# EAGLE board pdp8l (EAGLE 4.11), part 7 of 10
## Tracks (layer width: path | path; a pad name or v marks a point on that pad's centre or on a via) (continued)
N$34  (via drill 0.61) (continued)
  Route2 0.203: v25.6,207.52 25.6,207.92 v57.3,239.62
  Route15 0.203: v9.75,135.59 34.14,111.2 35.76,111.2 C34.K1
  Bottom 0.203: v7.32,197.76 8.13,198.58 16.26,198.58 25.2,207.52 v25.6,207.52 | v57.3,239.62 57.71,240.03 73.15,240.03 73.97,240.84 AB31.AM1
N$35  (via drill 0.61)
  Top 0.203: v7.72,112.01 6.5,113.23 6.5,134.77 7.32,135.59 7.32,147.78 6.1,149 6.1,203.05 12.19,209.14 12.19,216.86 10.97,218.08 v10.97,219.71
  Route2 0.203: v56.49,220.12 68.68,232.31 68.68,233.12 69.49,233.93 69.49,235.97 71.12,237.59 AB31.AN1
  Bottom 0.203: v7.72,112.01 13.01,106.73 32.11,106.73 32.92,107.54 C34.L1 | v10.97,219.71 11.38,219.3 12.19,219.3 13.82,217.68 48.77,217.68 51.61,220.52 56.08,220.52 v56.49,220.12
N$36  (via drill 0.61)
  Top 0.203: v310.9,55.12 310.9,38.05 311.71,37.24 311.71,33.17 312.52,32.36 D12.N1
  Route15 0.203: v310.9,55.12 306.02,60 303.99,60 D13.C1
N$37
  Route2 0.203: D12.F1 312.93,51.46 312.93,53.09 334.06,74.22 335.69,74.22 343,81.53 343,83.16 343.81,83.97 345.85,83.97 347.07,85.19 C09.U2
N$38  (via drill 0.61)
  Top 0.203: v343.81,86 343.81,83.57 344.22,83.16 C09.V2 | v326.34,103.48 325.53,104.29 325.53,107.14 C11.L1
  Route15 0.203: v343.81,86 v326.34,103.48
N$39
  Top 0.203: A08.M2 359.66,241.66 357.63,243.69 357.63,244.09 A08.L2
  Route2 0.203: A10.R1 338.53,232.31 338.53,233.93 340.16,235.56 340.16,235.97 343.81,239.62 347.88,239.62 349.1,240.84 351.54,240.84 353.16,242.47 354.79,242.47 356.41,244.09 A08.L2
N$40  (via drill 0.61)
  Top 0.203: v102.01,259.54 102.01,235.56 117.04,220.52 117.04,211.99 117.45,211.58 117.45,136.8 112.98,132.33 112.98,130.71 C28.C1
  Bottom 0.203: v102.01,259.54 101.6,259.13 99.57,259.13 96.72,261.98 25.6,261.98 24.38,260.76 A35.E1
N$41  (via drill 0.61)
  Top 0.203: v307.24,131.93 307.64,132.33 307.64,142.49 308.05,142.9 308.05,147.37 307.64,147.78 307.64,159.16 307.24,159.56 307.24,160.78 307.64,161.19 v307.64,184.35 | v347.47,236.78 347.47,240.84 A09.M2 | v323.9,212.39 323.9,201.83 v321.87,199.8
  Route2 0.203: v307.64,184.35 312.12,188.82 314.15,188.82 315.37,190.04 B12.E1 316.18,191.26 317.81,192.89 317.81,195.73 v321.87,199.8 | v347.47,236.78 347.07,236.78 330.4,220.12 330.4,218.9 v323.9,212.39
  Route15 0.203: v307.24,131.93 308.05,131.12 308.05,129.9 308.46,129.49 308.46,129.08 310.49,127.05 310.49,125.83 310.9,125.42 311.3,125.42 316.18,120.55 316.18,120.14 316.59,119.74 316.18,119.33 314.96,119.33 314.15,120.14 313.33,120.14 C12.F1
N$42  (via drill 0.61)
  Route2 0.203: v315.37,120.14 313.33,118.11 313.33,114.86 C12.J1 | v251.97,211.99 251.97,213.21 280.42,241.66 280.42,242.06 280.82,242.47 282.45,242.47 286.11,246.13 286.92,246.13 289.76,248.97 293.83,248.97 317.4,272.54 v317.4,273.76
  Route15 0.203: v315.37,120.14 310.08,125.42 310.08,126.64 308.05,128.68 308.05,129.08 299.92,137.21 299.92,142.9 297.89,144.93 297.89,146.15 296.67,147.37 296.67,149.4 295.86,150.22 295.86,151.44 289.36,157.94 289.36,162 273.51,177.85 273.1,177.85 269.85,181.1 269.85,182.73 264.97,187.6 264.97,188.42 254.41,198.98 254.41,203.45 254,203.86 254,209.96 v251.97,211.99 | v317.4,273.76 317.4,276.61 314.55,279.45 314.55,280.26 318.21,283.92 334.87,283.92 353.57,265.23 354.79,265.23 356.41,263.6 A08.D2
N$43  (via drill 0.61)
  Top 0.203: v327.96,180.29 330,180.29 330,188.01 v329.59,188.42 | v345.03,204.27 347.07,206.3 351.13,206.3 351.13,204.27 v351.94,203.45 | v355.6,220.12 357.23,221.74 357.23,223.77 356.82,224.18 356.01,224.18 356.01,227.43 357.23,228.65 357.23,231.09 A08.R2
  Route2 0.203: v303.99,112.83 303.99,115.27 308.05,119.33 308.05,120.14 314.15,126.24 314.15,127.05 v315.37,128.27 | v305.61,143.31 305.61,145.75 320.65,160.78 320.65,161.59 323.49,164.44 323.49,175.82 v327.96,180.29 | v329.59,188.42 329.59,188.82 v345.03,204.27 | v351.13,215.24 351.13,215.65 v355.6,220.12
  Route15 0.203: v303.99,112.83 312.52,104.29 312.52,102.26 C12.N1 | v315.37,128.27 315.37,128.68 314.55,129.49 314.55,133.55 306.02,142.09 306.02,142.9 v305.61,143.31 | v351.94,203.45 351.13,204.27 351.13,205.89 350.72,206.3 350.72,207.52 353.16,209.96 352.75,210.36 352.75,211.99 351.13,213.61 v351.13,215.24
N$44  (via drill 0.61)
  Top 0.203: v278.79,132.74 279.2,133.15 279.2,138.84 274.32,143.71 274.32,147.37 273.51,148.18 273.51,158.75 v273.91,159.16 | v316.59,231.5 v315.37,232.72
  Route2 0.203: v255.63,177.44 255.63,177.85 262.53,184.76 263.75,184.76 293.83,214.83 294.64,214.83 295.45,215.65 298.7,215.65 299.52,216.46 301.55,216.46 v316.59,231.5 | v315.37,232.72 315.77,232.72 317.4,234.34 317.4,238.4 v329.59,250.6
  Route15 0.203: v278.79,132.74 278.79,132.33 299.92,111.2 299.92,108.76 C13.L1 | v255.63,177.44 v273.91,159.16 | v329.59,250.6 330,250.6 340.56,240.03 342.19,240.03 343.81,238.4 A09.N2
N$45  (via drill 0.61)
  Top 0.203: A08.H2 360.07,254.66 360.07,259.54 A08.E2 | v342.6,156.72 343,157.12 343,255.88 343.81,256.69 A09.F2 344.22,257.91 344.22,262.79 A09.D2 | A09.E2 347.47,259.54 347.47,254.66 A09.H2
  Bottom 0.203: A08.F2 357.63,257.5 359.66,259.54 360.07,259.54 A08.E2 | v342.6,156.72 333.25,156.72 332.44,155.91 B10.T2 | 346.66,255.47 345.44,256.69 345.03,256.69 A09.F2 | 346.66,255.47 347.47,254.66 A09.H2 | 346.66,255.47 358.44,255.47 359.66,254.25 A08.H2
N$46
  Top 0.203: C13.H1 302.77,118.11 302.77,121.36 301.95,122.17 301.95,137.62 303.17,138.84 303.17,150.62 301.95,151.84 301.95,195.33 302.77,196.14 B13.C1
N$47  (via drill 0.61)
  Top 0.203: v342.19,248.97 342.6,248.56 342.6,164.44 340.16,162 340.16,151.44 340.56,151.03 340.56,139.24 339.75,138.43 339.75,90.88 340.16,90.47 340.16,82.75 342.6,80.31 342.6,39.68 343,39.27 343,25.04 343.41,24.64 343.41,20.57 344.22,19.76 D09.T2 | A09.H1 353.57,253.44 351.54,251.41 351.54,251 A09.J1
  Bottom 0.203: v342.19,248.97 346.25,248.97 347.47,250.19 350.32,250.19 A09.J1
N$48  (via drill 0.61)
  Top 0.203: v340.16,33.17 340.16,25.86 342.6,23.42 342.6,14.88 344.22,13.26 D09.V2
  Bottom 0.203: v340.16,33.17 340.56,33.58 346.25,33.58 347.07,34.39 D09.M2
N$49  (via drill 0.61)
  Top 0.203: A09.S2 347.47,227.84 347.47,222.96 A09.U2 347.07,221.74 345.03,221.74 345.03,224.99 A09.T2 344.22,226.21 344.22,231.09 A09.R2 | v330.4,32.77 330.4,72.19 329.18,73.41 329.18,84.38 330.4,85.6 330.4,103.48 v330.81,103.89 | v338.53,111.61 339.34,112.42 339.34,138.84 338.94,139.24 338.94,147.78 339.34,148.18 339.34,223.77 v340.56,224.99
  Route2 0.203: v338.53,111.61 v330.81,103.89
  Bottom 0.203: v330.4,32.77 326.34,32.77 325.93,32.36 D11.N1 | v340.56,224.99 343.81,224.99 A09.T2
N$50  (via drill 0.61)
  Top 0.203: A09.P1 353.57,235.56 353.57,240.84 A09.M1 | v324.31,215.24 324.71,214.83 324.71,201.83 323.49,200.61 323.49,99.82 322.68,99.01 C11.P2 | v349.5,215.24 349.5,227.43 350.72,228.65 350.72,231.09 A09.R1 350.72,232.31 350.72,237.59 A09.N1
  Route2 0.203: A09.P1 353.57,234.34 353.16,234.34 351.13,232.31 A09.R1
  Bottom 0.203: v324.31,215.24 324.71,215.65 349.1,215.65 v349.5,215.24
N$51  (via drill 0.61)
  Top 0.203: v320.65,131.93 v320.65,85.6 | v324.31,131.93 323.9,132.33 323.9,191.67 v324.31,192.07 | v321.87,192.07 321.06,192.89 v321.06,205.08 | v354.79,205.08 354.79,220.93 355.6,221.74 355.6,251.82 356.01,252.22 v356.01,261.57 | A08.A1 366.17,272.54 364.95,271.32 364.95,264.82 364.13,264.01 A08.D1
  Route2 0.203: v324.31,192.07 v321.87,192.07
  Route15 0.203: v324.31,131.93 v320.65,131.93
  Bottom 0.203: v320.65,85.6 316.59,85.6 C12.U1 | v321.06,205.08 321.46,205.49 354.38,205.49 v354.79,205.08 | v356.01,261.57 356.41,261.98 361.7,261.98 362.92,263.2 A08.D1
N$52  (via drill 0.61)
  Top 0.203: v305.21,185.98 305.21,185.57 304.39,184.76 304.39,179.07 303.58,178.26 B13.K1
  Bottom 0.203: v305.21,185.98 311.3,185.98 312.12,186.79 B12.F1
N$53  (via drill 0.61)
  Top 0.203: v273.51,169.32 273.51,167.28 273.91,166.88 273.91,163.22 273.1,162.41 273.1,147.78 273.91,146.96 273.91,142.49 273.51,142.09 273.51,122.17 274.32,121.36 C15.F1
  Route2 0.203: v273.51,169.32 273.51,169.72 v293.01,189.23
  Bottom 0.203: v293.01,189.23 295.45,189.23 296.27,190.04 B13.E2
N$54
  Bottom 0.203: B14.J2 280.82,180.29 280.82,175.82 280.01,175.82 279.6,175.41 279.6,173.38 311.3,173.38 312.12,174.19 B12.L1
N$55  (via drill 0.61)
  Top 0.203: v311.3,220.12 v311.3,228.65
  Bottom 0.203: v311.3,220.12 310.9,220.52 295.45,220.52 294.23,219.3 A13.V2 | v311.3,228.65 315.37,228.65 A12.S1
N$56  (via drill 0.61)
  Top 0.203: v293.01,179.48 292.2,180.29 292.2,204.67 290.98,205.89 290.98,220.12 292.2,221.34 v292.2,246.13 | A08.K1 366.17,248.16 366.17,248.56 364.13,250.6 A08.J1 364.13,251 364.13,251.41 366.17,253.44 A08.H1 366.17,254.25 366.17,254.66 364.13,256.69 A08.F1
  Route15 0.203: v293.01,179.48 294.23,178.26 296.27,178.26 B13.K2
  Bottom 0.203: v292.2,246.13 364.95,246.13 366.17,247.34 A08.K1
N$57  (via drill 0.61)
  Top 0.203: B09.H2 347.47,184.76 347.47,190.04 B09.E2 | B09.F2 344.22,188.01 344.22,192.89 B09.D2 | v323.09,207.92 323.09,212.8 323.49,213.21 323.49,252.63 322.68,253.44 A11.H2
  Route15 0.203: v323.09,207.92 323.09,206.7 334.47,195.33 335.28,195.33 336.91,193.7 336.91,192.89 340.56,189.23 342.19,189.23 343.81,187.6 B09.F2 345.03,186.79 347.07,184.76 347.07,184.35 B09.H2
N$58
  Top 0.203: B12.M1 316.18,172.16 317.4,173.38 317.4,185.57 316.99,185.98 316.99,189.64 317.4,190.04 317.4,271.32 316.18,272.54 A12.A1
N$59  (via drill 0.61)
  Top 0.203: B09.M2 347.47,172.16 347.47,177.04 B09.K2 | B09.N2 344.22,168.91 344.22,174.19 B09.L2 | v324.31,240.84 324.31,222.15 326.75,219.71 326.75,202.23 327.15,201.83 327.15,175.41 v327.56,175.01
  Route2 0.203: v324.31,240.84 322.68,240.84 A11.M2
  Bottom 0.203: v327.56,175.01 329.18,173.38 340.97,173.38 341.78,174.19 343.81,174.19 B09.L2 345.03,175.01 345.44,175.01 347.47,177.04 B09.K2
N$60  (via drill 0.61)
  Top 0.203: B09.N1 350.32,167.69 350.32,162.41 B09.R1 | v328.78,199.39 328.78,201.02 327.15,202.64 327.15,244.5 325.53,246.13 325.53,250.19 A11.J1 | B09.P1 353.57,165.66 353.57,170.94 B09.M1
  Route15 0.203: v328.78,199.39 353.57,174.6 353.57,172.16 B09.M1
  Bottom 0.203: B09.R1 351.13,162.41 353.16,164.44 353.57,164.44 B09.P1
N$61  (via drill 0.61)
  Top 0.203: B09.U2 347.07,152.65 345.03,154.69 345.03,155.09 B09.T2 345.03,155.91 345.03,156.31 347.07,158.34 B09.S2 347.07,159.16 345.03,161.19 345.03,161.59 B09.R2 | v330.4,170.13 330.4,188.82 330,189.23 330,201.42 331.22,202.64 331.22,203.45 330,204.67 330,242.47 327.15,245.31 327.15,261.16 325.53,262.79 A11.D1
  Route2 0.203: v330.4,170.13 330.4,168.91 v326.75,165.25
  Bottom 0.203: v326.75,165.25 326.75,162.41 330.4,162.41 331.22,163.22 343,163.22 343.81,162.41 B09.R2
N$62  (via drill 0.61)
  Top 0.203: v325.53,241.66 325.53,238.81 A11.N1 | A09.A1 353.57,273.76 352.75,274.57 351.54,274.57 351.54,270.1 A09.B1
  Route2 0.203: v325.53,241.66 331.62,247.75 331.62,248.56 349.1,266.04 349.1,268.07 350.32,269.29 A09.B1
N$63  (via drill 0.61)
  Top 0.203: v263.35,165.25 263.35,182.32 262.13,183.54 262.13,184.35 262.94,185.17 264.16,185.17 264.57,185.57 264.57,189.23 263.35,190.45 v263.35,196.14 | v258.88,205.08 257.66,206.3 257.66,213.21 262.13,217.68 263.35,217.68 263.35,220.52 v262.94,220.93
  Route2 0.203: v262.94,220.93 262.94,222.15 286.51,245.72 290.58,245.72 291.8,246.94 292.61,246.94 295.05,249.38 301.95,249.38 308.46,255.88 313.33,255.88 323.49,266.04 323.49,270.1 327.96,274.57 331.22,274.57 335.69,270.1 v336.09,270.51
  Route15 0.203: v263.35,165.25 263.35,164.85 290.17,138.02 291.39,138.02 302.36,127.05 302.36,125.42 302.77,125.02 303.99,125.02 309.27,119.74 309.27,118.11 C12.H2 | v263.35,196.14 263.35,196.54 260.5,199.39 260.5,203.45 v258.88,205.08
  Bottom 0.203: v336.09,270.51 336.91,271.32 338.94,271.32 341.78,268.48 361.29,268.48 362.51,269.7 362.92,269.7 A08.B1
N$64  (via drill 0.61)
  Top 0.203: v306.43,208.33 305.61,209.14 305.61,215.24 v306.02,215.65
  Route2 0.203: v306.43,208.33 305.61,207.52 305.61,204.67 304.39,203.45 304.39,202.23 293.83,191.67 293.83,188.01 B13.F2 | v306.02,215.65 310.49,220.12 310.49,220.52 310.9,220.93 312.52,220.93 318.21,226.62 320.24,226.62 321.06,227.43 321.06,229.46 v351.94,260.35
  Bottom 0.203: v351.94,260.35 353.97,262.38 360.48,262.38 364.54,266.45 366.17,266.45 A08.C1
N$65  (via drill 0.61)
  Top 0.203: v294.64,184.35 295.05,183.95 295.05,176.63 293.83,175.41 B13.L2 | v320.24,211.18 v320.24,227.84
  Route2 0.203: v294.64,184.35 299.11,188.82 299.11,189.64 313.74,204.27 313.74,204.67 v320.24,211.18
  Bottom 0.203: v320.24,227.84 320.65,228.24 321.46,228.24 A11.S2
N$66  (via drill 0.61)
  Top 0.203: v318.62,233.53 318.62,237.59 A11.N2
  Bottom 0.203: v318.62,233.53 314.55,233.53 313.33,232.31 A12.R1
N$67
  Top 0.203: C12.S2 310.08,92.51 310.9,93.32 310.9,109.17 309.68,110.39 C12.K2
N$68  (via drill 0.61)
  Top 0.203: v307.24,143.31 307.24,148.18 306.83,148.59 B12.V2 | v362.1,143.31 362.1,159.97 363.32,161.19 B08.R1
  Route2 0.203: B08.P1 366.57,164.44 366.17,164.44 364.13,162.41 B08.R1
  Bottom 0.203: v307.24,143.31 307.64,142.9 361.7,142.9 v362.1,143.31
N$69  (via drill 0.61)
  Top 0.203: v377.95,108.36 377.95,150.22 377.55,150.62 377.55,170.54 v377.14,170.94
  Route2 0.203: B08.N1 364.13,168.5 364.13,168.91 366.17,170.94 B08.M1
  Route15 0.203: v377.95,108.36 382.02,104.29 383.24,104.29 383.64,103.89 383.64,103.48 394.61,92.51 397.87,92.51 C05.S2
  Bottom 0.203: v377.14,170.94 375.11,172.97 368.61,172.97 367.39,171.75 B08.M1
N$70  (via drill 0.61)
  Top 0.203: v351.54,136.8 352.75,138.02 v352.75,160.78
  Route2 0.203: v322.27,106.73 331.22,115.67 332.03,115.67 333.25,116.89 333.25,117.7 335.28,119.74 335.28,120.55 v351.54,136.8
  Bottom 0.203: v322.27,106.73 311.71,106.73 310.08,105.1 C12.M2 | v352.75,160.78 353.57,161.59 356.41,161.59 B08.R2
N$71  (via drill 0.61)
  Route15 0.203: v327.96,161.59 327.96,162 v322.68,167.28
  Bottom 0.203: v327.96,161.59 329.18,161.59 330,160.78 337.31,160.78 338.12,159.97 358.85,159.97 359.66,159.16 B08.S2 | v322.68,167.28 322.27,166.88 318.21,166.88 315.37,169.72 301.95,169.72 300.74,168.5 B13.N1
N$72  (via drill 0.61)
  Top 0.203: v299.52,246.94 299.52,250.19 A13.J1
  Route2 0.203: v299.52,246.94 273.1,220.52 273.1,217.68 v269.04,213.61
  Route15 0.203: v269.04,213.61 270.66,211.99 270.66,209.96 271.07,209.55 271.07,205.89 298.3,178.66 298.3,177.85 300.33,175.82 300.74,175.82 312.12,164.44 v312.12,164.03
  Bottom 0.203: v312.12,164.03 312.93,164.85 315.37,164.85 B12.P1
N$73  (via drill 0.61)
  Top 0.203: v315.77,244.09 315.77,246.94 A12.K1
  Route2 0.203: v315.77,244.09 286.92,215.24 286.92,214.43 286.11,213.61 285.29,214.43 285.29,215.24 287.32,217.27 287.32,218.49 A14.V1
N$74  (via drill 0.61)
  Top 0.203: B08.F2 356.82,188.01 356.82,192.89 B08.D2 356.82,194.11 356.01,194.92 v356.01,205.89 | v301.95,205.89 301.95,229.46 300.33,231.09 A13.R1
  Bottom 0.203: v301.95,205.89 305.21,205.89 305.61,205.49 315.77,205.49 316.18,205.89 v356.01,205.89 | B08.E2 359.66,190.86 358.44,192.07 355.19,192.07 354.79,192.48 354.79,193.7 356.41,193.7 B08.D2
N$75
  Bottom 0.203: B14.P2 284.89,164.85 286.11,163.63 307.64,163.63 308.86,162.41 312.12,162.41 B12.R1
N$76  (via drill 0.61)
  Top 0.203: v299.52,92.51 298.7,93.32 v298.7,123.39 | v315.77,139.24 315.37,139.65 v315.37,148.59
  Route2 0.203: v299.52,92.51 302.77,92.51 C13.S1 | v298.7,123.39 303.58,128.27 304.8,128.27 v315.77,139.24
  Bottom 0.203: v315.37,148.59 314.96,149 313.33,149 B12.V1
N$77  (via drill 0.61)
  Top 0.203: v272.69,246.53 272.69,216.46 271.48,215.24 271.48,208.33 v271.88,207.92 | v315.37,163.22 315.77,162.81 315.77,159.56 B12.S1
  Route2 0.203: v272.69,246.53 286.11,259.94 289.76,259.94 A14.E1
  Route15 0.203: v271.88,207.92 271.88,205.89 294.23,183.54 295.05,183.54 v315.37,163.22
N$78  (via drill 0.61)
  Top 0.203: v278.38,192.07 276.76,193.7 276.76,195.73 275.95,196.54 275.95,213.21 274.73,214.43 274.73,215.65 275.13,216.05 275.13,216.86 274.32,217.68 273.51,217.68 273.51,239.22 v275.13,240.84
  Route2 0.203: v275.13,240.84 286.51,252.22 288.14,252.22 289.76,253.85 A14.H1
  Route15 0.203: v278.38,192.07 282.85,187.6 282.85,183.54 313.74,152.65 315.37,152.65 B12.U1
N$79
  Top 0.203: A14.J1 286.92,251.41 286.11,252.22 286.11,268.48 286.92,269.29 A14.B1
N$80  (via drill 0.61)
  Route2 0.203: v199.54,190.86 199.54,191.26 201.17,192.89 201.17,194.51 214.99,208.33 214.99,209.14 215.39,209.55 215.39,219.71 233.27,237.59 233.27,238 v258.06,262.79
  Route15 0.203: v199.54,190.86 203.61,186.79 203.61,185.98 251.16,138.43 251.16,135.59 263.35,123.39 263.35,122.58 280.82,105.1 280.82,102.26 C14.N2
  Bottom 0.203: v258.06,262.79 258.47,262.38 271.48,262.38 274.32,265.23 288.54,265.23 289.76,266.45 A14.C1
N$81  (via drill 0.61)
  Top 0.203: v268.63,87.22 267,87.22 267,112.83 266.6,113.23 266.6,131.12 267,131.52 267,137.62 268.63,139.24 v268.63,145.75 | v290.17,224.99 289.36,225.81 289.36,244.5 291.8,246.94 291.8,271.73 290.98,272.54 A14.A1
  Route2 0.203: v268.63,87.22 278.38,96.98 284.89,96.98 286.92,99.01 286.92,101.04 C14.N1 | v245.06,176.63 243.84,177.85 248.31,182.32 249.53,182.32 251.16,183.95 251.16,185.17 264.16,198.17 268.63,198.17 272.69,202.23 272.69,206.7 284.07,218.08 284.07,218.9 v290.17,224.99
  Route15 0.203: v268.63,145.75 270.66,145.75 272.69,147.78 249.53,170.94 249.53,171.75 245.06,176.22 v245.06,176.63
N$82  (via drill 0.61)
  Top 0.203: v232.05,176.63 232.05,180.7 232.87,181.51 232.87,182.73 231.65,183.95 v231.65,207.52
  Route2 0.203: v231.65,207.52 231.65,208.33 237.74,214.43 237.74,216.05 283.26,261.57 285.7,261.57 286.92,262.79 A14.D1
  Route15 0.203: v232.05,176.63 235.31,173.38 235.31,167.28 258.88,143.71 258.88,142.49 263.75,137.62 263.75,135.99 281.63,118.11 283.67,118.11 C14.H2
N$83  (via drill 0.61)
  Top 0.203: 295.45,229.87 295.05,230.28 295.05,233.12 294.23,233.93 294.23,237.59 A13.N2 | 295.45,229.87 296.27,229.06 A13.S2 | v303.99,143.31 304.39,143.71 304.39,156.72 v303.99,157.12 304.39,157.12 304.39,166.06 303.99,166.47 303.99,167.28 304.8,168.1 304.8,175.01 305.61,175.82 305.61,177.85 v305.21,178.26 | 295.45,229.87 294.64,229.06 v294.64,228.65
  Route2 0.203: v288.95,143.31 282.45,136.8 282.45,120.14 280.82,118.52 283.67,115.67 283.67,111.61 C14.K2 | v294.64,228.65 294.64,228.24 284.89,218.49 284.89,209.55 v281.63,206.3
  Route15 0.203: v281.63,206.3 281.63,203.05 282.85,201.83 282.85,200.61 v305.21,178.26
  Bottom 0.203: v303.99,143.31 v288.95,143.31 | v303.99,157.12 305.21,158.34 308.86,158.34 B12.S2
N$84  (via drill 0.61)
  Route2 0.203: v265.79,213.61 270.26,218.08 270.26,218.9 293.42,242.06 293.42,243.69 A13.L2
  Route15 0.203: v265.79,213.61 265.79,213.21 266.19,212.8 266.19,204.27 266.6,203.86 266.6,197.76 304.39,159.97 304.39,157.94 306.02,156.31 B12.T2
N$85
  Route2 0.203: C14.K1 290.17,111.61 290.17,115.27 287.73,117.7 304.8,134.77 304.8,135.99 316.59,147.78 316.59,148.59 323.49,155.5 323.49,157.53 323.9,157.94 323.9,159.97 325.12,161.19 B11.R1
N$86
  Top 0.203: B11.N1 325.93,168.91 326.75,169.72 326.75,201.42 325.93,202.23 325.93,218.49 A11.V1
N$87  (via drill 0.61)
  Top 0.203: v299.11,190.86 298.7,191.26 298.7,204.67 295.86,204.67 291.8,208.74 291.8,213.61 295.05,216.86 295.05,224.18 294.23,224.99 A13.T2
  Route15 0.203: v299.11,190.86 312.12,177.85 313.74,177.85 324.71,166.88 326.34,166.88 327.96,165.25 B11.P1
N$88
  Route2 0.203: C14.D1 288.14,127.05 288.14,127.46 290.17,129.49 C14.C1
N$89  (via drill 0.61)
  Route2 0.203: v254.81,166.88 253.19,168.5 289.36,204.67 298.3,204.67 309.27,215.65 309.27,216.05 309.68,216.46 313.74,216.46 314.15,216.86 314.96,216.86 318.62,220.52 319.84,220.52 321.46,222.15 A11.U2
  Route15 0.203: v254.81,166.88 275.54,146.15 275.54,142.49 276.76,141.28 276.76,139.65 280.01,136.4 277.98,134.37 277.98,132.33 279.6,130.71 279.6,126.24 280.82,125.02 280.82,121.36 C14.F2
N$90  (via drill 0.61)
  Top 0.203: v280.42,128.68 280.01,129.08 280.01,132.33 279.6,132.74 279.6,163.22 282.45,166.06 v282.45,170.94 | v320.24,209.14 318.62,210.77 318.62,218.49 A11.V2
  Route2 0.203: v284.07,109.17 282.45,110.79 282.45,114.86 279.6,117.7 279.6,127.86 v280.42,128.68 | v282.45,170.94 283.67,169.72 284.48,169.72 285.29,170.54 285.29,171.35 286.92,172.97 287.73,172.97 298.3,183.54 298.3,185.17 299.11,185.98 300.74,185.98 301.55,186.79 301.55,190.86 305.61,194.92 310.9,194.92 v316.59,200.61
  Route15 0.203: v284.07,109.17 286.92,106.32 288.14,106.32 289.36,105.1 289.36,103.89 310.49,82.75 312.12,82.75 C12.V1 | v316.59,200.61 316.59,201.83 320.24,205.49 318.62,207.11 318.62,208.33 319.84,209.55 v320.24,209.14
N$91  (via drill 0.61)
  Top 0.203: v280.82,145.75 280.82,148.59 B14.V2 | C13.H2 296.67,118.11 295.45,119.33 v295.45,145.34 295.45,145.75 295.45,160.38 v295.86,160.78 | v310.08,160.38 310.08,164.03 309.68,164.44 B12.P2
  Bottom 0.203: v295.45,145.34 281.23,145.34 v280.82,145.75 | v310.08,160.38 309.68,160.78 v295.86,160.78
N$92  (via drill 0.61)
  Top 0.203: v294.64,86.82 295.05,87.22 295.05,99.82 294.23,100.63 294.23,101.04 C13.N2 293.42,102.26 293.42,107.14 C13.L2
  Bottom 0.203: v294.64,86.82 294.23,87.22 281.23,87.22 281.23,83.16 C14.V2
N$93  (via drill 0.61)
  Top 0.203: v295.05,110.79 295.05,100.63 296.67,99.01 C13.P2 | v276.76,113.23 279.2,115.67 279.2,126.64 276.35,129.49 v276.35,138.02
  Route2 0.203: v276.35,138.02 276.35,140.06 286.11,149.81 286.11,150.22 295.86,159.97 296.27,159.97 296.67,160.38 296.67,162 301.95,167.28 301.95,168.1 307.64,173.79 307.64,175.41 309.27,177.04 B12.K2
  Bottom 0.203: v295.05,110.79 293.01,112.83 277.17,112.83 v276.76,113.23
N$94  (via drill 0.61)
  Top 0.203: v294.23,164.44 292.2,162.41 292.2,151.03 293.42,149.81 B13.V2
  Bottom 0.203: v294.23,164.44 294.64,164.85 296.27,164.85 B13.P2
N$95  (via drill 0.61)
  Top 0.203: v308.05,159.97 308.05,182.32 309.27,183.54 B12.H2
  Bottom 0.203: v308.05,159.97 298.3,159.97 297.49,159.16 B13.S2
N$96  (via drill 0.61)
  Top 0.203: v306.43,179.07 306.43,175.41 B12.L2
  Route2 0.203: v306.43,179.07 323.49,196.14 323.49,197.76 325.12,199.39 B11.B1
N$97  (via drill 0.61)
  Top 0.203: v308.05,192.48 308.05,187.2 306.83,185.98 306.83,181.51 B12.J2
  Bottom 0.203: v308.05,192.48 321.06,192.48 321.87,193.29 324.71,193.29 B11.D1
N$98  (via drill 0.61)
  Route2 0.203: v251.16,263.2 199.54,211.58 199.54,209.14 197.92,207.52 197.51,207.52 126.8,136.8 126.8,135.99 108.92,118.11 106.88,118.11 C28.H2
  Route15 0.203: v251.16,263.2 254,263.2 258.06,259.13 262.13,259.13 288.54,232.72 288.54,231.09 288.95,230.68 288.95,222.96 284.07,218.08 286.92,215.24 286.92,214.43 287.73,213.61 287.73,212.39 293.83,206.3 293.83,204.67 294.23,204.27 294.23,202.23 295.45,201.02 295.45,200.2 310.9,184.76 310.9,182.32 v310.08,181.51
  Bottom 0.203: v310.08,181.51 312.12,179.48 320.65,179.48 322.27,181.1 324.71,181.1 B11.J1
N$99
  Bottom 0.203: D11.K2 322.68,41.71 324.71,43.74 325.12,43.74 D11.J1
N$100  (via drill 0.61)
  Top 0.203: v317.81,189.23 319.02,190.45 319.02,192.89 B11.D2
  Bottom 0.203: v317.81,189.23 308.05,189.23 306.83,188.01 B12.F2
N$101  (via drill 0.61)
  Route2 0.203: v249.94,124.21 249.94,125.02 259.28,134.37 259.28,135.18 271.07,146.96 271.07,147.78 289.36,166.06 289.36,167.69 299.11,177.44 299.11,177.85 307.64,186.38 307.64,188.82 308.86,190.04 B12.E2
  Route15 0.203: v249.94,124.21 259.69,114.45 259.69,113.64 279.6,93.73 281.23,93.73 282.45,92.51 283.67,92.51 C14.S2
N$102  (via drill 0.61)
  Route2 0.203: v319.43,54.71 319.43,51.46 D11.F2
  Bottom 0.203: v319.43,54.71 319.84,55.12 329.59,55.12 330.4,54.3 334.47,54.3 D10.E2
N$103  (via drill 0.61)
  Top 0.203: v327.15,55.93 327.15,42.52 327.96,41.71 D11.K1
  Bottom 0.203: v327.15,55.93 320.65,55.93 319.84,56.74 D11.D2
N$104
  Top 0.203: D11.F1 325.12,51.46 324.31,52.27 324.31,62.03 325.12,62.84 D11.B1
N$105
  Bottom 0.203: D11.C1 329.18,60 330.4,58.78 336.5,58.78 337.72,57.56 D10.D1
N$106  (via drill 0.61)
  Top 0.203: v337.31,166.88 337.72,166.47 337.72,162.41 B10.R1
  Bottom 0.203: v337.31,166.88 336.09,166.88 332.03,170.94 330,170.94 329.18,170.13 327.96,170.13 327.56,170.54 323.09,170.54 322.68,170.94 B11.M2
N$107  (via drill 0.61)
  Top 0.203: v26.01,110.79 25.6,111.2 25.6,144.12 28.45,146.96 28.45,189.23 v27.64,190.04
  Route2 0.203: v13.82,191.67 14.22,191.67 25.2,202.64 25.2,203.45 33.33,211.58 34.14,211.58 53.65,231.09 53.65,235.15 54.86,236.37 58.93,236.37 66.24,243.69 66.24,245.31 67.87,246.94 AB31.AK2
  Route15 0.203: v26.01,110.79 32.92,103.89 32.92,102.26 C34.N1
  Bottom 0.203: v27.64,190.04 26.82,189.23 22.76,189.23 21.13,190.86 19.1,190.86 18.29,191.67 v13.82,191.67
N$108  (via drill 0.61)
  Top 0.203: v233.68,77.06 234.49,77.88 234.49,133.55 231.65,136.4 231.65,170.54 v230.02,172.16 | v283.67,214.83 282.85,215.65 282.85,222.96 284.07,224.18 284.07,227.84 A14.S2
  Route2 0.203: v230.02,172.16 230.02,172.57 262.53,205.08 262.53,205.49 v264.57,207.52
  Route15 0.203: v233.68,77.06 234.09,77.06 242.21,68.94 242.21,68.53 258.06,52.68 260.5,52.68 260.91,52.27 262.53,52.27 292.2,22.61 292.2,18.54 297.49,13.26 299.52,13.26 D13.V1
  Bottom 0.203: v264.57,207.52 271.07,214.02 282.85,214.02 v283.67,214.83
N$109
  Bottom 0.203: AB07.BJ1 376.73,180.7 377.55,179.88 381.61,179.88 383.24,178.26 385.27,178.26 AB06.BK2
N$110
  Bottom 0.203: AB06.BJ1 389.74,180.7 391.36,179.07 397.05,179.07 397.87,178.26 AB05.BK2
N$111
  Bottom 0.203: AB04.BJ1 414.93,180.7 416.56,179.07 421.84,179.07 423.06,177.85 AB03.BK2
N$112
  Bottom 0.203: AB03.BJ1 427.53,180.7 429.16,179.07 435.25,179.07 436.07,178.26 AB02.BK2
N$113
  Route2 0.203: D36.V2 2.03,13.26 2.03,15.29 29.26,42.52 33.33,42.52 79.25,88.44 79.25,89.66 80.87,91.29 C30.S2
N$114  (via drill 0.61)
  Top 0.203: v23.16,20.57 28.45,20.57 28.45,25.04 31.7,28.3 31.7,77.88 41.05,87.22 41.05,104.29 v39.01,106.32
  Bottom 0.203: v23.16,20.57 2.85,20.57 2.03,19.76 D36.T2 | v39.01,106.32 39.42,106.73 49.17,106.73 52.43,109.98 79.65,109.98 80.47,110.79 C30.K2
N$115
  Route2 0.203: D36.S2 4.47,23.01 4.47,26.67 1.63,29.52 2.85,30.73 2.85,41.3 4.06,42.52 4.47,42.52 4.88,42.93 4.88,44.15 6.1,45.36 6.1,51.05 19.91,64.87 19.91,66.09 69.9,116.08 69.9,116.89 76,122.99 76,124.61 77.62,126.24 C30.D2
N$116  (via drill 0.61)
  Top 0.203: v316.18,180.7 314.15,182.73 314.15,203.45 313.74,203.86 313.74,204.67 314.15,205.08 315.77,205.08 315.77,203.86 B12.A1
  Route2 0.203: B12.A1 316.59,203.45 316.59,203.86 331.22,218.49 A10.V2
  Route15 0.203: v316.18,180.7 v337.31,159.56
  Bottom 0.203: v337.31,159.56 340.16,159.56 340.56,159.16 B10.S1
N$117  (via drill 0.61)
  Top 0.203: v11.79,81.94 12.19,81.53 12.19,72.59 6.5,66.9 6.5,30.33 5.28,29.11 D36.P2
  Bottom 0.203: v11.79,81.94 20.73,90.88 64.21,90.88 66.65,93.32 84.12,93.32 86.56,90.88 92.25,90.88 93.07,91.69 C29.S2
N$118
  Route2 0.203: D36.M2 5.28,35.2 9.35,35.2 13.41,39.27 18.69,39.27 44.7,65.28 44.7,66.9 56.49,78.69 57.3,78.69 57.71,79.1 64.21,79.1 91.85,106.73 91.85,108.76 93.47,110.39 C29.K2
N$119
  Route2 0.203: D36.K2 5.28,41.71 5.28,43.74 22.35,60.81 22.35,62.03 58.12,97.79 59.33,97.79 86.56,125.02 88.19,125.02 89.81,126.64 C29.D2
N$120  (via drill 0.61)
  Top 0.203: v96.72,58.78 96.72,62.84 D29.B1
  Bottom 0.203: D36.B1 8.53,64.06 9.35,64.87 18.29,64.87 18.69,64.47 19.51,64.47 23.57,68.53 39.01,68.53 42.27,65.28 88.19,65.28 88.59,64.87 95.5,64.87 96.32,64.06 D29.B1 | v96.72,58.78 120.29,58.78 121.51,57.56 D27.D1
N$121
  Bottom 0.203: D36.D1 8.53,56.74 13.01,56.74 13.82,55.93 94.69,55.93 95.5,56.74 96.32,56.74 D29.D1 97.54,56.74 98.75,55.52 123.55,55.52 124.77,54.3 D27.E1
N$122  (via drill 0.61)
  Top 0.203: v119.48,51.87 119.48,51.46 123.95,46.99 123.95,42.52 124.77,41.71 D27.K1
  Bottom 0.203: 98.75,52.68 99.57,53.49 D29.E1 | 98.75,52.68 98.35,52.27 13.01,52.27 11.79,53.49 D36.E1 | v119.48,51.87 118.67,52.68 98.75,52.68
N$123
  Route15 0.203: B10.V1 337.72,149.81 337.72,154.28 336.91,155.09 336.91,158.75 315.37,180.29 315.37,181.91 306.02,191.26 306.02,192.07 305.21,192.89 305.21,198.17 303.17,200.2 303.17,201.42 301.95,202.64 301.95,204.67 303.17,205.89 308.86,205.89 310.9,203.86 310.9,202.23 312.52,200.61 B12.B1
N$124  (via drill 0.61)
  Top 0.203: v9.75,55.93 9.75,49.02 10.57,48.21 D36.H1 | v95.5,55.52 v95.5,48.62 | v106.07,39.27 98.75,39.27 98.75,46.18 99.57,46.99 D29.H1
  Bottom 0.203: v9.75,55.93 10.16,55.52 v95.5,55.52 | v95.5,48.62 95.91,48.21 99.57,48.21 D29.H1 | v106.07,39.27 120.7,39.27 121.51,38.46 D27.L1
N$125
  Route15 0.203: D27.R1 121.51,25.45 117.86,25.45 100.79,42.52 99.16,42.52 97.54,44.15 D29.J1
  Bottom 0.203: D36.J1 8.53,44.15 9.75,42.93 95.1,42.93 96.32,44.15 D29.J1
N$126
  Bottom 0.203: D36.L1 8.53,38.46 9.35,39.27 95.5,39.27 96.32,38.46 D29.L1 97.54,37.64 98.35,36.83 114.61,36.83 124.36,27.08 125.17,27.08 125.17,23.01 D27.S1
N$127
  Route2 0.203: D27.H2 118.26,47.4 115.42,47.4 106.48,38.46 105.26,38.46 103.63,36.83 102.41,36.83 100.79,35.2 D29.M1
  Bottom 0.203: D36.M1 11.79,34.8 13.41,33.17 98.35,33.17 99.57,34.39 D29.M1
N$128  (via drill 0.61)
  Top 0.203: v114.2,32.77 114.2,42.11 115.82,43.74 D27.J2
  Bottom 0.203: 98.75,29.92 99.57,29.11 D29.P1 | 98.75,29.92 98.35,30.33 13.41,30.33 11.79,28.7 D36.P1 | v114.2,32.77 111.35,29.92 98.75,29.92
N$129
  Bottom 0.203: 98.75,23.42 99.57,22.61 D29.S1 | 98.75,23.42 98.35,23.83 13.01,23.83 11.79,22.61 D36.S1 | 98.75,23.42 109.73,23.42 112.98,26.67 115.42,26.67 115.42,31.14 D27.N2
N$130
  Route15 0.203: D27.P2 118.67,29.11 118.67,31.14 94.69,55.12 92.66,55.12 91.03,56.74 D29.D2
  Bottom 0.203: D36.D2 2.03,57.56 3.25,58.78 88.59,58.78 89.81,57.56 D29.D2
N$131  (via drill 0.61)
  Top 0.203: v122.33,52.68 126.8,48.21 126.8,11.23 121.51,11.23 121.11,11.63 121.11,13.66 119.48,15.29 D27.U2
  Bottom 0.203: D36.E2 5.28,54.3 6.1,55.12 92.25,55.12 93.07,54.3 D29.E2 94.28,54.3 95.5,54.3 96.32,55.12 119.89,55.12 v122.33,52.68
N$132  (via drill 0.61)
  Top 0.203: v99.16,14.48 98.35,15.29 98.35,34.8 95.1,38.05 95.1,45.77 93.88,46.99 D29.H2
  Bottom 0.203: D36.H2 5.28,48.21 6.1,49.02 91.85,49.02 93.07,47.8 D29.H2 | v99.16,14.48 114.2,14.48 115.42,13.26 D27.V2
N$133  (via drill 0.61)
  Route15 0.203: v106.07,62.43 109.32,59.18 109.32,57.96 D28.D1
  Bottom 0.203: D35.B1 21.13,62.84 21.95,62.03 82.5,62.03 83.31,62.84 83.72,62.84 D30.B1 84.94,63.25 86.16,62.03 105.66,62.03 v106.07,62.43
N$134  (via drill 0.61)
  Top 0.203: v21.54,61.21 21.54,58.78 20.73,57.96 D35.D1 | v83.31,61.62 84.12,60.81 84.12,57.96 D30.D1 | v113.79,61.62 114.2,61.21 114.2,55.93 112.98,54.71 D28.E1
  Bottom 0.203: v21.54,61.21 21.95,61.62 v83.31,61.62 83.72,61.62 v113.79,61.62
N$135  (via drill 0.61)
  Top 0.203: v89,45.36 88.59,45.77 88.59,52.68 87.78,53.49 D30.E1
  Bottom 0.203: D35.E1 24.38,53.49 25.2,52.68 85.34,52.68 86.56,53.9 D30.E1 | v89,45.36 89.41,45.77 97.54,45.77 100.79,42.52 111.35,42.52 112.17,41.71 D28.K1
N$136  (via drill 0.61)
  Top 0.203: v89,42.11 87.78,43.33 87.78,46.99 D30.H1
  Bottom 0.203: D35.H1 24.38,47.4 25.6,46.18 83.31,46.18 84.53,47.4 86.56,47.4 D30.H1 | v89,42.11 91.44,39.68 103.63,39.68 104.85,38.46 108.92,38.46 D28.L1
N$137  (via drill 0.61)
  Top 0.203: D30.J1 83.72,43.74 v83.72,42.11 83.72,41.71 83.72,40.49 88.59,35.61 88.59,28.7 v90.22,27.08
  Route15 0.203: v21.54,40.08 20.73,40.89 20.73,43.74 D35.J1
  Bottom 0.203: v21.54,40.08 21.95,39.68 81.28,39.68 v83.72,42.11 | v90.22,27.08 107.7,27.08 108.92,25.86 D28.R1
N$138  (via drill 0.61)
  Top 0.203: v91.44,20.98 85.34,27.08 85.34,36.83 84.53,37.64 D30.L1
  Bottom 0.203: D35.L1 21.13,37.64 21.95,36.83 82.91,36.83 83.72,37.64 D30.L1 | v91.44,20.98 111.35,20.98 112.17,21.79 D28.S1
N$139  (via drill 0.61)
  Route2 0.203: v91.85,35.2 104.04,47.4 105.66,47.4 D28.H2
  Bottom 0.203: D35.M1 24.38,35.2 25.6,36.42 85.34,36.42 86.56,35.2 D30.M1 87.78,35.2 v91.85,35.2
N$140
  Route2 0.203: D28.J2 102.82,43.74 102.82,42.11 91.03,30.33 89,30.33 87.78,29.11 D30.P1
  Bottom 0.203: D35.P1 24.38,28.3 25.6,27.08 85.34,27.08 86.56,28.3 D30.P1
N$141
  Top 0.203: D28.N2 102.82,31.14 101.19,29.52 101.19,12.04 95.91,6.76 91.85,6.76 91.85,15.7 87.78,19.76 87.78,21.79 D30.S1
  Bottom 0.203: D35.S1 24.38,21.79 25.2,20.98 85.34,20.98 86.56,22.2 D30.S1
N$142  (via drill 0.61)
  Route15 0.203: v82.5,56.74 106.07,33.17 106.07,29.11 D28.P2
  Bottom 0.203: D35.D2 15.04,57.56 15.85,58.37 76.4,58.37 77.22,57.56 D30.D2 78.44,56.74 v82.5,56.74
N$143  (via drill 0.61)
  Top 0.203: v19.1,65.28 19.1,55.93 17.88,54.71 D35.E2 | v72.34,70.56 79.65,70.56 79.65,55.93 80.87,54.71 D30.E2
  Route15 0.203: D28.U2 106.07,16.51 106.07,20.57 104.85,21.79 104.85,25.86 92.25,38.46 92.25,40.49 82.91,49.84 82.91,51.87 81.28,53.49 D30.E2
  Bottom 0.203: v19.1,65.28 23.98,70.16 71.93,70.16 v72.34,70.56
N$144  (via drill 0.61)
  Top 0.203: v78.84,41.71 80.47,43.33 80.47,46.99 D30.H2
  Route15 0.203: D28.V2 102.82,13.26 102.82,15.7 82.09,36.42 81.69,36.42 81.28,36.83 81.28,38.86 78.84,41.3 v78.84,41.71
  Bottom 0.203: v78.84,41.71 77.22,40.08 23.16,40.08 22.35,40.89 21.13,40.89 20.32,40.08 6.5,40.08 6.5,44.96 7.32,45.77 15.04,45.77 16.66,47.4 D35.H2
N$145  (via drill 0.61)
  Top 0.203: v119.08,77.47 120.7,79.1 120.7,95.76 123.55,98.6 123.55,125.02 122.33,126.24 C27.D1
  Route2 0.203: v119.08,77.47 84.53,42.93 82.91,42.93 81.69,41.71 D30.K2
  Bottom 0.203: D35.K2 17.88,41.71 18.69,42.52 79.65,42.52 80.47,41.71 D30.K2
N$146  (via drill 0.61)
  Top 0.203: v125.17,74.22 126.8,75.84 126.8,99.01 123.95,101.85 123.95,105.51 126.8,108.36 126.8,122.58 125.98,123.39 C27.E1
  Route2 0.203: v125.17,74.22 124.77,74.22 120.29,69.75 119.08,69.75 112.98,63.65 111.76,63.65 84.94,36.83 83.31,36.83 81.69,35.2 D30.M2
  Bottom 0.203: D35.M2 17.88,34.39 18.69,33.58 79.65,33.58 80.47,34.39 D30.M2
N$147  (via drill 0.61)
  Top 0.203: v85.34,109.98 85.34,47.4 82.91,44.96 82.91,30.73 81.28,29.11 D30.P2
  Bottom 0.203: D35.P2 17.88,29.11 18.69,29.92 79.65,29.92 80.47,29.11 D30.P2 | v85.34,109.98 123.95,109.98 124.77,110.79 C27.K1
N$148  (via drill 0.61)
  Top 0.203: v78.84,66.5 76.4,64.06 76.4,35.2 79.65,31.95 79.65,24.23 80.87,23.01 D30.S2
  Route2 0.203: v78.84,66.5 119.89,107.54 121.51,107.54 C27.L1
  Bottom 0.203: D35.S2 17.88,22.61 18.69,23.42 79.65,23.42 80.47,22.61 D30.S2
N$149  (via drill 0.61)
  Top 0.203: v121.11,62.43 121.11,93.73 121.92,94.54 C27.R1
  Route2 0.203: v121.11,62.43 117.86,62.43 91.03,35.61 91.03,34.39 79.65,23.01 79.65,21.39 78.03,19.76 D30.T2
  Bottom 0.203: D35.T2 15.04,18.95 16.26,17.73 76.4,17.73 77.22,18.54 D30.T2
N$150
  Route2 0.203: C27.S1 124.77,91.69 120.7,91.69 107.29,78.28 106.88,78.28 105.26,76.66 105.26,69.34 78.03,42.11 78.03,40.49 76.4,38.86 76.4,14.07 77.22,13.26 D30.V2
  Bottom 0.203: D35.V2 15.04,12.85 16.26,14.07 76.4,14.07 77.22,13.26 D30.V2
N$151  (via drill 0.61)
  Top 0.203: v265.79,7.98 288.54,30.73 288.54,41.3 291.8,44.55 291.8,53.49 296.27,53.49 D13.E2 | v95.5,7.57 95.5,36.83 93.88,38.46 93.88,40.49 D29.K2
  Route15 0.203: v73.97,62.84 93.07,43.74 93.07,41.71 D29.K2
  Bottom 0.203: v73.97,62.84 71.93,64.87 35.76,64.87 32.51,68.12 28.45,68.12 27.23,66.9 27.23,64.87 28.85,64.87 29.67,64.06 32.92,64.06 D34.B1 | v265.79,7.98 265.38,8.38 240.18,8.38 238.56,6.76 211.33,6.76 210.92,6.35 182.47,6.35 181.25,7.57 v95.5,7.57
N$152  (via drill 0.61)
  Top 0.203: v37.39,71.37 34.54,68.53 34.54,59.18 33.33,57.96 D34.D1
  Route2 0.203: v171.09,13.26 172.72,14.88 175.16,12.45 175.97,12.45 181.25,17.73 205.23,17.73 208.48,20.98 253.19,20.98 268.22,36.02 269.85,36.02 280.01,46.18 290.98,46.18 292.2,47.4 296.27,47.4 D13.H2
  Route15 0.203: v37.39,71.37 41.45,67.31 41.45,66.09 65.02,42.52 81.69,42.52 82.91,41.3 84.12,41.3 91.03,34.39 93.07,34.39 D29.M2
  Bottom 0.203: v171.09,13.26 169.06,11.23 128.02,11.23 123.55,15.7 123.55,27.08 122.73,27.08 116.23,33.58 109.73,33.58 106.88,36.42 95.5,36.42 94.28,35.2 D29.M2
N$153  (via drill 0.61)
  Top 0.203: v44.7,26.26 41.05,26.26 v41.05,54.3 | v267.41,8.38 291.8,32.77 291.8,40.89 296.27,40.89 D13.K2 | v94.69,11.63 95.1,12.04 95.1,26.67 93.88,27.89 D29.P2
  Bottom 0.203: v44.7,26.26 45.11,26.67 87.38,26.67 88.59,27.89 92.66,27.89 93.07,28.3 D29.P2 | v41.05,54.3 36.98,54.3 D34.E1 | v267.41,8.38 267,8.79 239.78,8.79 238.15,7.16 210.92,7.16 210.51,6.76 182.88,6.76 181.66,7.98 98.35,7.98 v94.69,11.63
N$154  (via drill 0.61)
  Top 0.203: v38.61,20.17 35.36,20.17 35.36,38.05 37.8,40.49 37.8,46.18 36.98,46.99 D34.H1 | v273.51,9.6 292.2,28.3 292.2,39.27 294.64,39.27 295.86,38.05 295.86,36.42 296.67,35.61 D13.M2
  Bottom 0.203: 80.47,20.57 39.01,20.57 v38.61,20.17 | 80.47,20.57 87.38,20.57 88.59,21.79 93.07,21.79 D29.S2 | v273.51,9.6 273.1,9.2 239.37,9.2 237.74,7.57 210.51,7.57 210.11,7.16 183.29,7.16 182.07,8.38 99.16,8.38 93.07,14.48 86.56,14.48 80.47,20.57
N$155  (via drill 0.61)
  Top 0.203: v35.76,57.56 32.11,53.9 32.11,45.77 32.92,44.96 D34.J1 | v121.92,153.06 123.55,154.69 123.55,156.31 122.33,157.53 122.33,159.97 123.55,161.19 123.55,196.54 121.11,198.98 121.11,212.8 v121.51,213.21
  Route2 0.203: v35.76,57.56 44.3,66.09 44.3,69.75 47.14,72.59 47.14,79.5 105.66,138.02 106.88,138.02 v121.92,153.06
  Route15 0.203: v121.51,213.21 121.51,215.65 84.94,252.22 80.87,252.22 63.8,269.29 63.8,270.92 62.18,272.54 A32.A1
N$156  (via drill 0.61)
  Top 0.203: v130.05,131.52 130.05,158.34 127.2,161.19 127.2,185.98 126.8,186.38 126.8,199.8 123.55,203.05 123.55,227.03 v121.51,229.06
  Route2 0.203: v130.05,131.52 106.07,107.54 105.66,107.54 36.58,38.46 34.14,38.46 D34.L1
  Route15 0.203: v121.51,229.06 v87.78,262.79
  Bottom 0.203: v87.78,262.79 87.38,262.38 53.65,262.38 52.83,263.2 A32.D2
N$157  (via drill 0.61)
  Top 0.203: D11.R1 325.93,25.86 327.96,27.89 327.96,28.3 D11.P1 | v57.3,176.63 57.3,188.82 60.15,191.67 60.15,198.17 58.93,199.39 B32.B1 | v257.66,26.67 254.41,29.92 v254.41,32.77
  Route2 0.203: v21.54,141.28 22.76,141.28 26.42,144.93 26.42,145.75 v57.3,176.63
  Route15 0.203: v182.07,44.55 118.67,107.95 118.67,109.58 117.86,110.39 117.86,116.48 98.75,135.59 98.75,136.8 59.74,175.82 58.52,175.82 57.71,176.63 v57.3,176.63
  Bottom 0.203: v21.54,141.28 13.82,141.28 13.41,141.68 7.72,141.68 7.72,133.96 C36.B1 | v257.66,26.67 323.49,26.67 324.71,25.45 D11.R1 | v254.41,32.77 254,33.17 249.94,33.17 246.28,36.83 189.79,36.83 v182.07,44.55
N$158  (via drill 0.61)
  Top 0.203: D11.R2 319.84,25.45 321.87,27.48 321.87,27.89 D11.P2 | v2.03,125.42 3.25,126.64 3.25,154.69 v5.28,156.72
  Route2 0.203: v40.23,191.67 v5.28,156.72
  Route15 0.203: v139.4,193.29 194.26,138.43 196.29,138.43 231.65,103.07 237.34,103.07 261.31,79.1 262.94,79.1 263.35,78.69 264.16,78.69 265.79,77.06 265.79,76.66 281.23,61.21 281.23,59.59 314.96,25.86 318.62,25.86 D11.R2
  Bottom 0.203: v2.03,125.42 3.25,126.64 7.32,126.64 C36.D1 | v40.23,191.67 40.64,192.07 56.9,192.07 58.12,193.29 B32.D1 59.33,193.29 60.96,193.29 65.43,188.82 87.38,188.82 90.63,192.07 135.33,192.07 136.14,192.89 138.99,192.89 v139.4,193.29
N$159  (via drill 0.61)
  Top 0.203: v41.05,122.17 44.3,118.92 44.3,89.66 38.2,83.57 38.2,36.83 36.98,35.61 D34.M1
  Route2 0.203: v41.05,122.17 41.05,125.42 50.8,135.18 50.8,138.02 79.65,166.88 79.65,168.1 82.09,170.54 82.09,180.29 82.91,181.1 82.91,182.73 87.38,187.2 87.38,188.82 88.59,190.04 88.59,194.51 v102.41,208.33
  Route15 0.203: v102.41,208.33 102.41,211.58 60.55,253.44 60.55,255.47 59.33,256.69 A32.F1
N$160  (via drill 0.61)
  Top 0.203: D11.U2 321.46,16.1 319.43,18.14 319.43,18.54 D11.T2 | v103.63,2.29 89,2.29 89,3.5 84.53,7.98 22.35,7.98 22.35,67.72 15.85,74.22 15.85,120.95 13.41,123.39 11.79,123.39 C36.E1
  Route2 0.203: v4.88,125.83 25.2,146.15 26.01,146.15 44.3,164.44 44.3,168.5 54.86,179.07 54.86,181.51 60.15,186.79 60.15,188.82 61.37,190.04 B32.E1 | v103.63,2.29 104.04,2.69 108.1,2.69 108.92,3.5 190.19,3.5 190.6,3.91 247.5,3.91 249.53,5.94 288.95,5.94 290.17,7.16 299.92,7.16 300.74,7.98 302.77,7.98 305.61,10.82 307.24,10.82 314.96,18.54 318.62,18.54 D11.T2
  Bottom 0.203: v4.88,125.83 8.94,125.83 10.57,124.21 C36.E1
N$161  (via drill 0.61)
  Top 0.203: v16.66,93.73 19.51,96.57 19.51,141.68 21.54,143.71 21.54,144.53 20.73,145.34 16.26,145.34 16.26,173.79 16.66,174.19 16.66,176.63 15.44,177.85 15.44,203.45 v13.82,205.08
  Bottom 0.203: v16.66,93.73 1.63,93.73 1.63,89.66 C36.T2 | v13.82,205.08 13.41,205.49 7.32,205.49 2.44,210.36 2.44,218.08 2.85,218.08 6.5,221.74 6.5,229.87 38.2,229.87 39.01,229.06 39.83,229.06 40.23,229.46 40.23,231.09 39.83,231.09 A33.R2
N$162  (via drill 0.61)
  Top 0.203: v115.42,111.61 117.04,113.23 117.04,123.8 111.35,129.49 111.35,182.32 v111.76,182.73
  Route2 0.203: v115.42,111.61 36.98,33.17 36.98,29.11 D34.P1
  Route15 0.203: v111.76,182.73 111.76,183.13 76.4,218.49 76.4,222.96 67.06,232.31 67.06,233.93 57.3,243.69 57.3,245.31 55.68,246.94 A32.K2
N$163
  Top 0.203: A33.S2 42.67,227.84 42.67,222.96 A33.U2
  Route15 0.203: A33.T2 40.23,224.99 40.64,224.99 42.67,222.96 A33.U2
N$164  (via drill 0.61)
  Top 0.203: B32.J1 58.52,180.29 58.52,176.63 56.9,175.01 56.9,157.12 v56.49,156.72 56.9,156.72 56.9,149 58.12,147.78 58.12,143.71 v59.33,142.49
  Route2 0.203: v59.33,142.49 v41.86,125.02
  Route15 0.203: v219.05,68.53 210.11,68.53 165.41,113.23 165.41,118.11 145.49,138.02 143.05,138.02 v123.14,157.94
  Bottom 0.203: v219.05,68.53 219.46,68.94 239.37,68.94 240.59,67.72 241.81,67.72 242.62,68.53 261.72,68.53 262.13,68.12 301.95,68.12 302.77,67.31 D13.A1 | v123.14,157.94 122.73,157.53 90.63,157.53 89.81,156.72 v56.49,156.72 | v41.86,125.02 38.2,121.36 36.98,121.36 28.45,112.83 9.75,112.83 8.53,114.05 C36.J1
N$165  (via drill 0.61)
  Route2 0.203: v2.44,158.75 10.57,166.88 v10.97,166.88 | v8.13,185.57 9.35,186.79 9.35,197.76 v50.39,238.81
  Route15 0.203: v2.44,158.75 2.85,158.34 2.85,109.98 9.35,103.48 9.35,97.38 9.75,96.98 9.75,91.29 18.69,82.35 18.69,80.72 27.23,72.19 27.23,66.09 28.45,64.87 28.45,53.09 28.85,52.68 28.85,46.99 32.11,43.74 32.11,30.73 36.17,26.67 36.17,23.01 D34.S1
  Bottom 0.203: v10.97,166.88 10.97,170.13 9.75,170.13 6.5,173.38 6.5,185.57 v8.13,185.57 | v50.39,238.81 51.61,240.03 56.49,240.03 57.3,240.84 61.37,240.84 A32.M1
N$166  (via drill 0.61)
  Top 0.203: D34.S2 29.67,21.79 28.85,20.98 28.85,15.29 33.73,10.41 89.81,10.41 89.81,12.45 D29.V2 | v120.7,46.99 120.7,48.21 117.86,51.05 117.86,116.08 118.67,116.89 C27.H2
  Route2 0.203: v120.7,46.99 120.7,44.96 92.25,16.51 92.25,14.48 91.03,13.26 D29.V2
N$167  (via drill 0.61)
  Top 0.203: v156.06,191.67 155.65,192.07 v155.65,195.73 | v60.55,199.39 60.55,185.57 61.37,184.76 B32.H1
  Route2 0.203: C36.H1 10.97,118.11 9.35,119.74 9.35,122.17 7.32,124.21 18.69,135.59 18.69,136.4 32.11,149.81 32.11,150.22 58.12,176.22 58.12,178.26 60.15,180.29 60.15,182.32 61.37,183.54 B32.H1 | v300.33,171.35 309.68,180.7 312.12,180.7 B12.J1
  Route15 0.203: v300.33,171.35 299.52,171.35 v284.89,185.98
  Bottom 0.203: v284.89,185.98 264.97,185.98 264.16,186.79 263.35,186.79 262.53,185.98 189.79,185.98 183.69,192.07 156.46,192.07 v156.06,191.67 | v155.65,195.73 153.21,198.17 134.93,198.17 134.52,197.76 132.89,197.76 132.49,198.17 103.23,198.17 102.82,197.76 101.19,197.76 100.38,198.58 76,198.58 75.59,198.98 72.34,198.98 71.93,198.58 61.37,198.58 v60.55,199.39
N$168  (via drill 0.61)
  Top 0.203: v298.7,1.88 298.7,42.52 299.92,43.74 D13.J1 | v88.19,3.1 21.95,3.1 21.95,34.8 15.44,41.3 15.44,98.6 13.01,101.04 13.01,104.7 10.16,107.54 8.53,107.54 C36.L1
  Route2 0.203: B32.L1 58.12,174.19 58.12,171.35 56.9,170.13 56.9,168.5 54.05,165.66 54.05,160.78 33.73,140.46 32.11,140.46 19.51,127.86 19.51,122.17 16.26,118.92 16.26,118.11 9.75,111.61 9.75,110.39 8.13,108.76 C36.L1
  Bottom 0.203: v298.7,1.88 105.66,1.88 104.44,3.1 v88.19,3.1
N$169  (via drill 0.61)
  Top 0.203: v295.45,2.69 295.45,16.51 298.3,19.36 298.3,26.67 297.08,27.89 D13.P2 | v15.44,14.48 12.6,14.48 12.6,103.48 11.79,104.29 C36.M1
  Route2 0.203: B32.M1 61.37,170.94 61.37,167.28 49.99,155.91 49.99,155.09 39.42,144.53 39.42,142.49 21.54,124.61 21.54,123.39 19.51,121.36 19.51,116.08 17.48,114.05 17.48,113.23 13.01,108.76 13.01,107.14 11.38,105.51 C36.M1
  Bottom 0.203: v295.45,2.69 295.05,2.29 106.07,2.29 104.85,3.5 89,3.5 78.03,14.48 v15.44,14.48
N$170  (via drill 0.61)
  Top 0.203: v22.76,107.95 25.2,105.51 25.2,59.59 26.82,57.96 D34.D2
  Route2 0.203: v8.94,179.48 8.94,179.88 9.35,180.29 9.35,184.35 10.57,185.57 10.57,187.6 12.6,189.64 12.6,194.11 19.91,201.42 21.54,201.42 21.95,201.83 21.95,203.45 23.16,204.67 23.98,204.67 26.42,207.11 26.42,207.92 48.36,229.87 49.99,229.87 51.61,231.5 A32.R2
  Route15 0.203: v52.02,125.42 51.21,126.24 51.21,131.52 39.42,143.31 39.42,146.56 12.6,173.38 12.6,174.19 9.75,177.04 9.75,178.66 v8.94,179.48
  Bottom 0.203: v22.76,107.95 24.79,109.98 33.33,109.98 48.77,125.42 v52.02,125.42
N$171  (via drill 0.61)
  Top 0.203: v107.7,3.5 107.7,3.1 287.32,3.1 287.32,3.91 291.8,8.38 291.8,21.79 296.27,21.79 D13.S2
  Route2 0.203: B32.P1 61.77,164.44 61.77,160.78 51.21,150.22 51.21,149 49.58,147.37 49.58,145.34 28.85,124.61 28.85,119.33 20.32,110.79 20.32,109.58 13.01,102.26 13.01,100.63 11.38,99.01 C36.P1
  Route15 0.203: v107.7,3.5 97.54,3.5 19.51,81.53 19.51,88.04 13.01,94.54 13.01,96.16 11.38,97.79 C36.P1
N$172  (via drill 0.61)
  Route2 0.203: v124.77,179.48 123.55,178.26 123.55,173.79 107.7,157.94 107.7,151.84 106.07,150.22 106.07,148.18 105.66,147.78 105.66,139.24 54.05,87.63 52.83,87.63 52.43,87.22 48.77,87.22 33.73,72.19 33.73,70.97 31.29,68.53 31.29,59.59 30.48,58.78 30.48,54.71 D34.E2
  Route15 0.203: v124.77,179.48 124.77,182.73 123.95,183.54 123.95,189.23 104.85,208.33 104.85,215.24 82.91,237.19 82.91,242.06 71.12,253.85 70.31,253.85 52.83,271.32 51.61,271.32 49.99,272.95 A33.A1
N$173  (via drill 0.61)
  Top 0.203: v296.67,3.5 296.67,15.29 D13.U2 | v15.44,17.32 13.01,17.32 13.01,91.29 v13.41,91.69
  Route2 0.203: B32.S1 61.77,157.94 61.77,155.09 53.65,146.96 53.65,146.15 49.99,142.49 49.99,140.87 47.55,138.43 47.55,136.8 35.36,124.61 35.36,119.74 34.54,118.92 34.54,117.7 25.6,108.76 25.6,104.29 13.41,92.1 v13.41,91.69
  Bottom 0.203: v296.67,3.5 295.05,3.5 294.23,2.69 106.48,2.69 105.26,3.91 89.41,3.91 76,17.32 v15.44,17.32 | v13.41,91.69 11.79,91.69 C36.S1
N$174  (via drill 0.61)
  Top 0.203: v3.25,160.78 3.25,158.34 2.85,157.94 2.85,128.27 2.03,127.46 C36.D2
  Route2 0.203: v3.25,160.78 3.66,160.78 v35.76,192.89 | v64.62,207.92 54.05,197.36 54.05,195.33 52.83,194.11 B32.D2
  Route15 0.203: v64.62,207.92 62.99,209.55 62.99,213.21 59.33,216.86 57.71,216.86 41.05,233.53 41.05,238.81 37.8,242.06 37.8,267.26 36.98,268.07 36.98,272.54 A34.A1
  Bottom 0.203: v35.76,192.89 36.17,192.48 50.8,192.48 51.61,193.29 B32.D2
N$175  (via drill 0.61)
  Route2 0.203: v2.85,163.22 2.85,194.51 3.25,194.92 3.25,215.65 4.06,216.46 4.06,220.93 1.63,223.37 37.8,259.54 37.8,261.16 39.42,262.79 A33.D2
  Route15 0.203: v2.85,163.22 4.88,161.19 3.25,159.56 3.25,110.39 9.75,103.89 9.75,97.79 12.6,94.94 12.6,94.13 19.1,87.63 19.1,81.13 28.85,71.37 28.85,53.49 29.67,52.68 29.67,48.21 D34.H2
N$176  (via drill 0.61)
  Top 0.203: v6.5,142.9 6.5,140.87 6.1,140.46 6.1,125.83 4.88,124.61 C36.E2 | v53.24,142.9 53.65,143.31 53.65,178.66 53.24,179.07 53.24,179.88 54.05,180.7 54.05,189.23 | 54.05,189.23 54.86,190.04 B32.E2 | v46.33,265.23 54.05,257.5 54.05,189.23
  Bottom 0.203: v53.24,142.9 v6.5,142.9 | v46.33,265.23 37.8,265.23 36.98,266.04 A34.C1
N$177  (via drill 0.61)
  Top 0.203: v60.55,264.82 60.55,215.65 62.99,213.21 62.99,206.3 57.3,200.61 57.3,189.64 56.08,188.42 56.08,184.76 B32.H2
  Route2 0.203: C36.H2 4.47,118.11 4.47,122.17 3.25,123.39 3.25,132.33 17.88,146.96 20.32,146.96 26.42,153.06 26.82,153.06 47.14,173.38 47.14,173.79 53.65,180.29 53.65,181.91 55.27,183.54 B32.H2
  Bottom 0.203: v60.55,264.82 51.61,264.82 49.17,262.38 34.95,262.38 34.14,263.2 A34.D1
N$178
  Route15 0.203: B32.P2 55.68,164.44 55.68,161.59 66.65,150.62 66.65,148.59 115.01,100.23 116.64,100.23 118.26,98.6 C27.P2
  Bottom 0.203: C36.P2 5.28,99.01 6.5,100.23 116.64,100.23 118.26,98.6 C27.P2
N$179  (via drill 0.61)
  Top 0.203: v6.5,80.31 6.5,89.66 4.88,91.29 C36.S2
  Route15 0.203: B32.S2 55.68,157.94 55.68,154.28 60.15,149.81 60.15,147.78 61.77,146.15 61.77,138.84 63.4,137.21 63.4,133.15 83.72,112.83 88.59,112.83 106.07,95.35 107.29,95.35 115.01,87.63 116.64,87.63 118.26,86 C27.U2
  Bottom 0.203: v6.5,80.31 7.32,79.5 115.82,79.5 118.67,82.35 118.67,85.19 C27.U2
N$180  (via drill 0.61)
  Top 0.203: v97.13,106.32 95.5,106.32 95.5,115.67 95.1,116.08 95.1,116.89 98.75,120.55 98.75,144.53 97.54,145.75 97.54,147.78 98.35,148.59 v98.35,156.72 | v55.27,201.42 56.9,201.42 56.9,206.7 54.46,209.14 54.46,216.86 60.15,222.56 60.15,257.91 46.74,271.32 44.7,271.32 44.7,259.13 45.92,257.91 A33.F1
  Route2 0.203: v97.13,106.32 79.65,88.85 79.65,88.04 33.33,41.71 30.89,41.71 D34.K2
  Route15 0.203: v98.35,156.72 98.35,158.34 v55.27,201.42
N$181  (via drill 0.61)
  Top 0.203: v49.17,149 49.58,148.59 49.58,138.02 50.39,137.21 50.39,127.05 47.95,124.61 v47.95,84.78
  Bottom 0.203: 50.39,82.75 51.61,83.97 114.61,83.97 115.42,83.16 C27.V2 | 50.39,82.75 48.77,81.13 2.85,81.13 2.03,81.94 C36.V2 | v49.17,149 51.61,149 B32.V2 | v47.95,84.78 49.99,82.75 50.39,82.75
N$182  (via drill 0.61)
  Top 0.203: v36.98,207.92 36.98,216.05 37.8,216.86 37.8,229.87 35.36,232.31 35.36,246.13 34.95,246.53 34.95,255.47 33.73,256.69 A34.F1
  Route2 0.203: v8.53,140.87 8.53,147.78 9.35,148.59 9.35,153.47 10.16,154.28 10.16,155.91 44.3,190.04 44.3,198.17 45.52,199.39 B33.B1
  Bottom 0.203: v8.53,140.87 8.94,140.87 15.44,134.37 19.1,134.37 19.91,133.55 C35.B1 | v36.98,207.92 34.95,205.89 25.2,205.89 24.79,205.49 24.79,204.27 27.23,204.27 30.07,201.42 44.3,201.42 45.11,200.61 45.52,200.61 B33.B1
N$183  (via drill 0.61)
  Top 0.203: v28.85,133.15 28.85,172.57 v31.7,175.41 | v40.64,252.22 41.45,251.41 41.45,216.05 38.61,213.21 38.61,209.14 43.08,204.67 44.3,204.67 44.3,195.33 45.52,194.11 B33.D1
  Route2 0.203: v28.85,133.15 23.16,127.46 21.13,127.46 C35.D1 | v31.7,175.41 31.7,175.82 35.36,179.48 35.36,180.29 44.7,189.64 44.7,191.67 45.92,192.89 B33.D1
  Bottom 0.203: v40.64,252.22 35.36,252.22 34.14,251 A34.J1
N$184  (via drill 0.61)
  Top 0.203: v20.32,131.52 21.95,129.9 21.95,110.79 25.6,107.14 25.6,67.72 28.45,64.87 28.45,30.33 29.67,29.11 D34.P2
